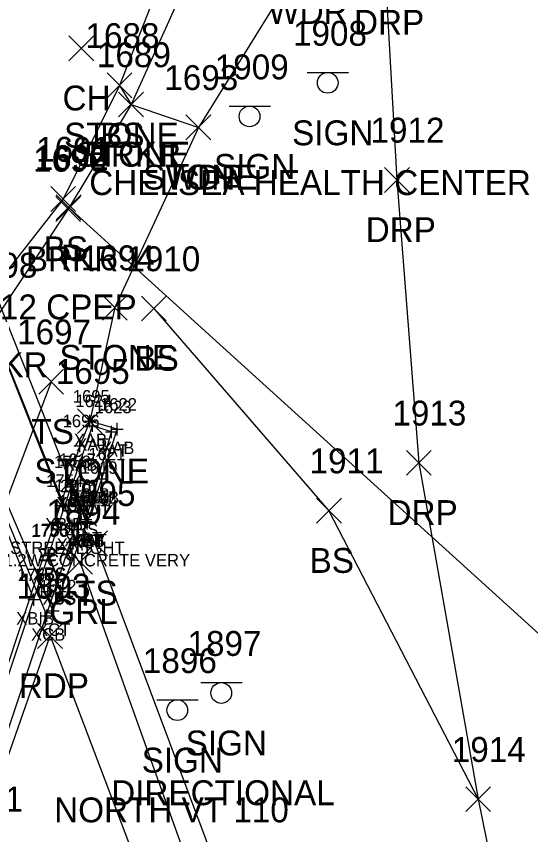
# Model space of a CAD drawing. Extents: x 1651305 to 1654558, y 539481 to 548441.
# Drawn here: x 1654353.9 to 1654395.2, y 544608.3 to 544674.1 of the extents above; entities that cross this region are included whole.
import ezdxf

# ---------------------------------------------------------------- set-up
doc = ezdxf.new("R2010")
doc.units = 0
for name, color, linetype in [('B_A', 7, 'Continuous'), ('B_C', 7, 'Continuous'), ('B_I', 7, 'Continuous'), ('B_TIC', 7, 'Continuous'), ('BB', 7, 'Continuous'), ('BDC', 7, 'Continuous'), ('BF', 7, 'Continuous'), ('BR', 7, 'Continuous'), ('BSE', 7, 'Continuous'), ('BSUBM', 7, 'Continuous'), ('D_A', 7, 'Continuous'), ('D_C', 7, 'Continuous'), ('D_I', 7, 'Continuous'), ('D_TIC', 7, 'Continuous'), ('DCP', 7, 'Continuous'), ('L_A', 7, 'Continuous'), ('L_I', 7, 'Continuous'), ('L_TIC', 7, 'Continuous'), ('LASF', 7, 'Continuous'), ('LAWA', 7, 'Continuous'), ('LAWE', 7, 'Continuous'), ('LELB', 7, 'Continuous'), ('P_A', 7, 'Continuous'), ('P_I', 7, 'Continuous'), ('P_TIC', 7, 'Continuous'), ('PET', 7, 'Continuous'), ('R_A', 7, 'Continuous'), ('R_I', 7, 'Continuous'), ('R_TIC', 7, 'Continuous'), ('RDP', 7, 'Continuous'), ('RGR', 7, 'Continuous'), ('S_A', 7, 'Continuous'), ('S_C', 7, 'Continuous'), ('S_I', 7, 'Continuous'), ('SSGN', 7, 'Continuous')]:
    doc.layers.add(name, color=color, linetype=linetype)

msp = doc.modelspace()

# ---------------------------------------------------------------- linework, layer by layer
at = {"layer": 'B_TIC'}
for p, q in [((1654359.785, 544641.57), (1654359.861, 544641.57)), ((1654359.993, 544641.203), (1654360.069, 544641.203)), ((1654359.993, 544641.203), (1654360.069, 544641.203)), ((1654361.974, 544640.927), (1654362.049, 544640.927)), ((1654361.542, 544640.707), (1654361.618, 544640.707)), ((1654358.994, 544639.588), (1654359.069, 544639.588)), ((1654360.754, 544636.929), (1654360.83, 544636.929)), ((1654358.254, 544636.307), (1654358.329, 544636.307)), ((1654358.396, 544636.474), (1654358.471, 544636.474)), ((1654358.396, 544636.474), (1654358.471, 544636.474)), ((1654360.131, 544635.843), (1654360.207, 544635.843)), ((1654357.622, 544634.79), (1654357.698, 544634.79)), ((1654358.058, 544634.399), (1654358.133, 544634.399)), ((1654359.05, 544634.353), (1654359.125, 544634.353)), ((1654359.462, 544633.672), (1654359.538, 544633.672)), ((1654358.367, 544633.155), (1654358.443, 544633.155)), ((1654359.477, 544633.501), (1654359.552, 544633.501)), ((1654359.477, 544633.501), (1654359.552, 544633.501)), ((1654359.477, 544633.501), (1654359.552, 544633.501)), ((1654359.565, 544633.364), (1654359.64, 544633.364)), ((1654359.606, 544633.46), (1654359.681, 544633.46)), ((1654356.437, 544630.766), (1654356.512, 544630.766)), ((1654356.476, 544630.821), (1654356.551, 544630.821)), ((1654357.233, 544628.812), (1654357.308, 544628.812)), ((1654357.272, 544628.867), (1654357.347, 544628.867)), ((1654355.297, 544627.225), (1654355.372, 544627.225)), ((1654356.325, 544625.929), (1654356.401, 544625.929)), ((1654356.819, 544626.314), (1654356.894, 544626.314))]:
    msp.add_line(p, q, dxfattribs=at)
for points in [[(1654359.282, 544641.57), (1654360.282, 544641.57)], [(1654359.782, 544641.07), (1654359.782, 544642.07)], [(1654359.99, 544640.703), (1654359.99, 544641.703)], [(1654359.99, 544640.703), (1654359.99, 544641.703)], [(1654359.49, 544641.203), (1654360.49, 544641.203)], [(1654359.49, 544641.203), (1654360.49, 544641.203)], [(1654361.47, 544640.927), (1654362.47, 544640.927)], [(1654361.539, 544640.207), (1654361.539, 544641.207)], [(1654361.97, 544640.427), (1654361.97, 544641.427)], [(1654361.039, 544640.707), (1654362.039, 544640.707)], [(1654358.49, 544639.588), (1654359.49, 544639.588)], [(1654358.99, 544639.088), (1654358.99, 544640.088)], [(1654358.392, 544635.974), (1654358.392, 544636.974)], [(1654358.392, 544635.974), (1654358.392, 544636.974)], [(1654360.251, 544636.929), (1654361.251, 544636.929)], [(1654360.751, 544636.429), (1654360.751, 544637.429)], [(1654357.75, 544636.307), (1654358.75, 544636.307)], [(1654357.892, 544636.474), (1654358.892, 544636.474)], [(1654357.892, 544636.474), (1654358.892, 544636.474)], [(1654358.25, 544635.807), (1654358.25, 544636.807)], [(1654360.128, 544635.343), (1654360.128, 544636.343)], [(1654359.628, 544635.843), (1654360.628, 544635.843)], [(1654357.619, 544634.29), (1654357.619, 544635.29)], [(1654358.054, 544633.899), (1654358.054, 544634.899)], [(1654357.119, 544634.79), (1654358.119, 544634.79)], [(1654357.554, 544634.399), (1654358.554, 544634.399)], [(1654358.546, 544634.353), (1654359.546, 544634.353)], [(1654359.046, 544633.853), (1654359.046, 544634.853)], [(1654358.364, 544632.655), (1654358.364, 544633.655)], [(1654358.959, 544633.672), (1654359.959, 544633.672)], [(1654359.459, 544633.172), (1654359.459, 544634.172)], [(1654359.473, 544633.001), (1654359.473, 544634.001)], [(1654359.473, 544633.001), (1654359.473, 544634.001)], [(1654359.473, 544633.001), (1654359.473, 544634.001)], [(1654359.561, 544632.864), (1654359.561, 544633.864)], [(1654359.602, 544632.96), (1654359.602, 544633.96)], [(1654357.864, 544633.155), (1654358.864, 544633.155)], [(1654358.973, 544633.501), (1654359.973, 544633.501)], [(1654358.973, 544633.501), (1654359.973, 544633.501)], [(1654358.973, 544633.501), (1654359.973, 544633.501)], [(1654359.061, 544633.364), (1654360.061, 544633.364)], [(1654359.102, 544633.46), (1654360.102, 544633.46)], [(1654356.433, 544630.266), (1654356.433, 544631.266)], [(1654356.472, 544630.321), (1654356.472, 544631.321)], [(1654355.933, 544630.766), (1654356.933, 544630.766)], [(1654355.972, 544630.821), (1654356.972, 544630.821)], [(1654357.229, 544628.312), (1654357.229, 544629.312)], [(1654357.268, 544628.367), (1654357.268, 544629.367)], [(1654356.729, 544628.812), (1654357.729, 544628.812)], [(1654356.768, 544628.867), (1654357.768, 544628.867)], [(1654355.293, 544626.725), (1654355.293, 544627.725)], [(1654354.793, 544627.225), (1654355.793, 544627.225)], [(1654356.322, 544625.429), (1654356.322, 544626.429)], [(1654356.815, 544625.814), (1654356.815, 544626.814)], [(1654355.822, 544625.929), (1654356.822, 544625.929)], [(1654356.315, 544626.314), (1654357.315, 544626.314)]]:
    msp.add_lwpolyline(points, dxfattribs=at)
at = {"layer": 'BB'}
for points in [[(1654329.217, 544706.64), (1654357.619, 544634.79)], [(1654326.61, 544699.426), (1654355.293, 544627.225)]]:
    msp.add_lwpolyline(points, dxfattribs=at)
at = {"layer": 'BDC'}
for points in [[(1654329.215, 544710.048), (1654328.717, 544711.198), (1654325.904, 544702.843), (1654343.99, 544656.168), (1654356.815, 544626.314), (1654359.561, 544633.364), (1654359.473, 544633.501)], [(1654325.775, 544701.967), (1654343.848, 544655.963), (1654356.322, 544625.929)]]:
    msp.add_lwpolyline(points, dxfattribs=at)
at = {"layer": 'BF'}
msp.add_lwpolyline([(1654329.215, 544710.048), (1654348.537, 544660.985), (1654359.473, 544633.501)], dxfattribs=at)
at = {"layer": 'BR'}
msp.add_lwpolyline([(1654329.215, 544710.048), (1654328.365, 544709.646), (1654348.062, 544658.92), (1654358.364, 544633.155), (1654359.473, 544633.501)], dxfattribs=at)
at = {"layer": 'BSE'}
for points in [[(1654358.25, 544636.307), (1654356.472, 544630.821), (1654356.433, 544630.766), (1654347.804, 544604.941), (1654347.754, 544604.896), (1654344.838, 544596.18), (1654344.825, 544596.158), (1654342.547, 544588.987), (1654343.343, 544587.033), (1654348.55, 544602.942), (1654348.6, 544602.987), (1654357.229, 544628.812), (1654357.268, 544628.867), (1654359.046, 544634.353)], [(1654359.046, 544634.353), (1654358.25, 544636.307)], [(1654357.229, 544628.812), (1654356.433, 544630.766)], [(1654357.268, 544628.867), (1654356.472, 544630.821)]]:
    msp.add_lwpolyline(points, dxfattribs=at)
at = {"layer": 'BSUBM'}
for points in [[(1654359.602, 544633.46), (1654360.751, 544636.929), (1654361.97, 544640.927), (1654359.782, 544641.57), (1654358.99, 544639.588), (1654343.132, 544591.581)], [(1654358.392, 544636.474), (1654359.459, 544633.672), (1654360.128, 544635.843), (1654361.539, 544640.707), (1654359.99, 544641.203)], [(1654358.392, 544636.474), (1654359.99, 544641.203)]]:
    msp.add_lwpolyline(points, dxfattribs=at)
at = {"layer": 'D_TIC'}
for points in [[(1654357.089, 544657.757), (1654359.089, 544659.757)], [(1654359.089, 544657.757), (1654357.089, 544659.757)]]:
    msp.add_lwpolyline(points, dxfattribs=at)
at = {"layer": 'DCP'}
msp.add_lwpolyline([(1654358.089, 544658.757), (1654409.494, 544612.147)], dxfattribs=at)
at = {"layer": 'L_TIC'}
for points in [[(1654358.101, 544670.552), (1654360.101, 544672.552)], [(1654360.101, 544670.552), (1654358.101, 544672.552)], [(1654361.172, 544667.564), (1654363.172, 544669.564)], [(1654363.172, 544667.564), (1654361.172, 544669.564)], [(1654361.172, 544667.564), (1654363.172, 544669.564)], [(1654363.172, 544667.564), (1654361.172, 544669.564)], [(1654362.102, 544666.03), (1654364.102, 544668.03)], [(1654364.102, 544666.03), (1654362.102, 544668.03)], [(1654362.102, 544666.03), (1654364.102, 544668.03)], [(1654364.102, 544666.03), (1654362.102, 544668.03)], [(1654367.514, 544664.191), (1654369.514, 544666.191)], [(1654369.514, 544664.191), (1654367.514, 544666.191)], [(1654367.514, 544664.191), (1654369.514, 544666.191)], [(1654369.514, 544664.191), (1654367.514, 544666.191)], [(1654356.638, 544658.428), (1654358.638, 544660.428)], [(1654358.638, 544658.428), (1654356.638, 544660.428)], [(1654357.045, 544657.626), (1654359.045, 544659.626)], [(1654359.045, 544657.626), (1654357.045, 544659.626)], [(1654360.8, 544649.702), (1654362.8, 544651.702)], [(1654362.8, 544649.702), (1654360.8, 544651.702)], [(1654363.93, 544649.628), (1654365.93, 544651.628)], [(1654365.93, 544649.628), (1654363.93, 544651.628)], [(1654355.673, 544643.744), (1654357.673, 544645.744)], [(1654357.673, 544643.744), (1654355.673, 544645.744)], [(1654358.782, 544640.57), (1654360.782, 544642.57)], [(1654360.782, 544640.57), (1654358.782, 544642.57)], [(1654378.02, 544633.378), (1654380.02, 544635.378)], [(1654380.02, 544633.378), (1654378.02, 544635.378)], [(1654359.198, 544630.754), (1654361.198, 544632.754)], [(1654361.198, 544630.754), (1654359.198, 544632.754)], [(1654390.022, 544610.182), (1654392.022, 544612.182)], [(1654392.022, 544610.182), (1654390.022, 544612.182)]]:
    msp.add_lwpolyline(points, dxfattribs=at)
at = {"layer": 'LASF'}
msp.add_lwpolyline([(1654362.172, 544668.564), (1654363.102, 544667.03), (1654368.514, 544665.191), (1654361.8, 544650.702), (1654359.782, 544641.57)], dxfattribs=at)
at = {"layer": 'LAWA'}
msp.add_lwpolyline([(1654379.782, 544856.85), (1654381.229, 544808.018), (1654382.76, 544783.063), (1654377.997, 544758.08), (1654381.891, 544756.134), (1654381.663, 544736.714), (1654380.899, 544705.776), (1654381.561, 544700.356), (1654376.773, 544678.508), (1654368.514, 544665.191)], dxfattribs=at)
at = {"layer": 'LAWE'}
msp.add_lwpolyline([(1654375.942, 544856.312), (1654377.084, 544805.548), (1654378.901, 544780.845), (1654375.25, 544758.971), (1654375.205, 544735.185), (1654374.977, 544710.304), (1654371.319, 544695.811), (1654368.773, 544679.567), (1654363.102, 544667.03), (1654358.045, 544658.626), (1654352.364, 544650.107), (1654344.898, 544634.32), (1654334.876, 544605.424), (1654326.397, 544588.829), (1654321.275, 544565.187), (1654313.301, 544530.304), (1654300.219, 544501.736), (1654283.171, 544465.466), (1654261.064, 544441.258)], dxfattribs=at)
at = {"layer": 'LELB'}
for points in [[(1654374.336, 544855.823), (1654375.217, 544803.448), (1654375.073, 544780.813), (1654373.472, 544758.468), (1654373.912, 544734.871), (1654373.922, 544712.905), (1654369.617, 544696.27), (1654366.919, 544680.671), (1654362.172, 544668.564), (1654357.638, 544659.428), (1654350.702, 544650.566), (1654343.252, 544636.932), (1654333.619, 544607.274), (1654325.309, 544589.171), (1654319.064, 544565.656), (1654310.743, 544531.111), (1654298.268, 544501.75), (1654282.289, 544466.342), (1654260.011, 544442.906)], [(1654364.93, 544650.628), (1654379.02, 544634.378), (1654391.022, 544611.182)], [(1654356.673, 544644.744), (1654348.436, 544623.035), (1654339.079, 544597.886)], [(1654360.198, 544631.754), (1654372.116, 544599.924), (1654382.811, 544567.633), (1654386.584, 544556.384), (1654391.723, 544539.804)]]:
    msp.add_lwpolyline(points, dxfattribs=at)
at = {"layer": 'P_TIC'}
for points in [[(1654355.582, 544623.309), (1654357.582, 544625.309)], [(1654357.582, 544623.309), (1654355.582, 544625.309)]]:
    msp.add_lwpolyline(points, dxfattribs=at)
at = {"layer": 'PET'}
msp.add_lwpolyline([(1654345.042, 544588.36), (1654350.59, 544607.191), (1654356.582, 544624.309), (1654366.692, 544597.705), (1654378.699, 544565.627), (1654388.798, 544536.019), (1654394.392, 544506.433), (1654399.121, 544481.008), (1654401.125, 544462.893), (1654401.531, 544436.346), (1654401.825, 544421.309), (1654397.366, 544359.696), (1654394.392, 544336.586), (1654391.404, 544308.963), (1654388.941, 544290.736), (1654386.845, 544274.06), (1654380.974, 544229.445), (1654377.749, 544202.908), (1654375.628, 544181.037), (1654372.192, 544149.754), (1654366.612, 544105.723), (1654362.798, 544072.788)], dxfattribs=at)
at = {"layer": 'R_TIC'}
for points in [[(1654383.483, 544659.968), (1654385.483, 544661.968)], [(1654385.483, 544659.968), (1654383.483, 544661.968)], [(1654385.242, 544637.223), (1654387.242, 544639.223)], [(1654387.242, 544637.223), (1654385.242, 544639.223)], [(1654357.986, 544629.265), (1654359.986, 544631.265)], [(1654359.986, 544629.265), (1654357.986, 544631.265)], [(1654390.022, 544610.182), (1654392.022, 544612.182)], [(1654392.022, 544610.182), (1654390.022, 544612.182)]]:
    msp.add_lwpolyline(points, dxfattribs=at)
at = {"layer": 'RDP'}
msp.add_lwpolyline([(1654389.401, 544756.56), (1654387.7, 544737.059), (1654385.299, 544704.988), (1654383.543, 544677.638), (1654384.483, 544660.968), (1654386.242, 544638.223), (1654391.022, 544611.182), (1654397.72, 544578.233), (1654402.202, 544552.331), (1654401.972, 544539.048), (1654399.157, 544531.466), (1654397.052, 544530.18)], dxfattribs=at)
at = {"layer": 'RGR'}
msp.add_lwpolyline([(1654358.986, 544630.265), (1654369.998, 544599.511), (1654381.164, 544566.937), (1654383.241, 544561.31), (1654386.584, 544556.384), (1654392.02, 544552.375)], dxfattribs=at)
at = {"layer": 'SSGN'}
for p, q in [((1654377.268, 544669.606), (1654380.602, 544669.606)), ((1654378.915, 544668.772), (1654378.915, 544668.772)), ((1654370.983, 544666.904), (1654374.316, 544666.904)), ((1654372.629, 544666.071), (1654372.629, 544666.071)), ((1654368.707, 544620.557), (1654372.04, 544620.557)), ((1654365.171, 544619.176), (1654368.504, 544619.176)), ((1654370.353, 544619.723), (1654370.353, 544619.723)), ((1654366.817, 544618.343), (1654366.817, 544618.343))]:
    msp.add_line(p, q, dxfattribs=at)
for centre in [(1654378.915, 544668.772), (1654372.629, 544666.071), (1654370.353, 544619.723), (1654366.817, 544618.343)]:
    msp.add_circle(centre, 0.833, dxfattribs=at)

# ---------------------------------------------------------------- texts
at = {"layer": 'B_A'}
for s, p in [('XAB', (1654358.502, 544639.57)), ('XAT', (1654358.694, 544639.203)), ('XAT', (1654358.694, 544639.203)), ('XAT', (1654360.244, 544638.707)), ('XAB', (1654360.691, 544638.927)), ('XAB', (1654357.711, 544637.588)), ('XAB', (1654359.471, 544634.929)), ('XBS', (1654356.991, 544634.307)), ('XAT', (1654357.097, 544634.474)), ('XAT', (1654357.097, 544634.474)), ('XAT', (1654358.833, 544633.843)), ('XBIB', (1654356.19, 544632.79)), ('XSF', (1654356.814, 544632.399)), ('XBS', (1654357.786, 544632.353)), ('XFAT', (1654357.729, 544631.501)), ('XAT', (1654358.163, 544631.672)), ('XCT', (1654358.194, 544631.501)), ('XRF', (1654358.233, 544631.501)), ('XCT', (1654358.282, 544631.364)), ('XAB', (1654358.323, 544631.46)), ('XRF', (1654357.124, 544631.155)), ('XBS', (1654355.173, 544628.766)), ('XBS', (1654355.212, 544628.821)), ('XBS', (1654355.969, 544626.812)), ('XBS', (1654356.008, 544626.867)), ('XBIB', (1654353.864, 544625.225)), ('XCT', (1654355.536, 544624.314)), ('XCB', (1654355.058, 544623.929))]:
    msp.add_text(s, height=1, dxfattribs=at).set_placement(p)
at = {"layer": 'B_C'}
for s, p in [('STREETLIGHT', (1654353.374, 544630.899)), ('XRF 3.3H X 1.2W CONCRETE VERY', (1654345.338, 544629.899))]:
    msp.add_text(s, height=1, dxfattribs=at).set_placement(p)
at = {"layer": 'B_I'}
for s, p in [('1695', (1654358.412, 544643.07)), ('1624', (1654358.62, 544642.703)), ('1624', (1654358.62, 544642.703)), ('1622', (1654360.6, 544642.427)), ('1623', (1654360.169, 544642.207)), ('1696', (1654357.593, 544641.088)), ('1753', (1654356.904, 544637.807)), ('1617', (1654357.306, 544637.974)), ('1617', (1654357.306, 544637.974)), ('1621', (1654359.664, 544638.429)), ('1619', (1654359.038, 544637.343)), ('1754', (1654356.272, 544636.29)), ('1616', (1654356.94, 544635.899)), ('2276', (1654357.389, 544635.853)), ('1618', (1654358.372, 544635.172)), ('1613', (1654357.277, 544634.655)), ('1620', (1654358.189, 544634.96)), ('1615', (1654358.387, 544635.001)), ('1615', (1654358.387, 544635.001)), ('1615', (1654358.387, 544635.001)), ('1614', (1654358.475, 544634.864)), ('1756', (1654355.059, 544632.266)), ('1755', (1654355.126, 544632.321)), ('2274', (1654355.599, 544630.312)), ('2275', (1654355.638, 544630.367)), ('1757', (1654353.947, 544628.725)), ('1611', (1654355.519, 544627.429)), ('1612', (1654355.729, 544627.814))]:
    msp.add_text(s, height=1, dxfattribs=at).set_placement(p)
at = {"layer": 'D_A'}
msp.add_text('P', height=2, dxfattribs=at).set_placement((1654357.467, 544653.757))
at = {"layer": 'D_C'}
msp.add_text('12 CPEP', height=2, dxfattribs=at).set_placement((1654352.554, 544649.757))
at = {"layer": 'D_I'}
msp.add_text('1692', height=2, dxfattribs=at).set_placement((1654355.349, 544661.757))
at = {"layer": 'L_A'}
for s, p in [('WDR', (1654374.135, 544673.508)), ('CH', (1654357.589, 544666.552)), ('STONE', (1654357.716, 544663.564)), ('BS', (1654360.613, 544663.564)), ('STONE', (1654358.645, 544662.03)), ('BRKR', (1654359.693, 544662.03)), ('STONE', (1654364.058, 544660.191)), ('WDR', (1654365.876, 544660.191)), ('BS', (1654356.079, 544654.428)), ('BRKR', (1654354.636, 544653.626)), ('STONE', (1654357.343, 544645.702)), ('BS', (1654363.371, 544645.628)), ('BRKR', (1654348.955, 544645.107)), ('TS', (1654355.083, 544639.744)), ('STONE', (1654355.325, 544636.57)), ('BS', (1654377.461, 544629.378)), ('TS', (1654358.608, 544626.754))]:
    msp.add_text(s, height=2, dxfattribs=at).set_placement(p)
at = {"layer": 'L_I'}
for s, p in [('1688', (1654359.432, 544671.564)), ('1688', (1654359.432, 544671.564)), ('1689', (1654360.354, 544670.03)), ('1689', (1654360.354, 544670.03)), ('1693', (1654365.774, 544668.191)), ('1693', (1654365.774, 544668.191)), ('1691', (1654355.465, 544662.428)), ('1690', (1654355.219, 544661.626)), ('1694', (1654359.06, 544653.702)), ('1910', (1654362.718, 544653.628)), ('1698', (1654349.624, 544653.107)), ('1697', (1654353.933, 544647.744)), ('1695', (1654357.042, 544644.57)), ('1911', (1654377.461, 544637.378)), ('1895', (1654357.506, 544634.754)), ('1914', (1654388.896, 544614.182))]:
    msp.add_text(s, height=2, dxfattribs=at).set_placement(p)
at = {"layer": 'P_A'}
msp.add_text('RDP', height=2, dxfattribs=at).set_placement((1654354.07, 544619.309))
at = {"layer": 'P_I'}
for s, p in [('1893', (1654353.889, 544627.309)), ('1891', (1654348.464, 544610.191)), ('1891', (1654348.464, 544610.191))]:
    msp.add_text(s, height=2, dxfattribs=at).set_placement(p)
at = {"layer": 'R_A'}
for s, p in [('DRP', (1654381.032, 544672.638)), ('DRP', (1654381.971, 544655.968)), ('DRP', (1654383.73, 544633.223)), ('GRL', (1654356.529, 544625.265))]:
    msp.add_text(s, height=2, dxfattribs=at).set_placement(p)
at = {"layer": 'R_I'}
for s, p in [('1912', (1654382.357, 544663.968)), ('1913', (1654384.116, 544641.223)), ('1894', (1654356.293, 544633.265)), ('1914', (1654388.896, 544614.182))]:
    msp.add_text(s, height=2, dxfattribs=at).set_placement(p)
at = {"layer": 'S_A'}
for p in [(1654376.053, 544663.752), (1654369.767, 544661.051), (1654367.491, 544614.703), (1654363.955, 544613.323)]:
    msp.add_text('SIGN', height=2, dxfattribs=at).set_placement(p)
at = {"layer": 'S_C'}
for s, p in [('CHELSEA HEALTH CENTER', (1654359.739, 544659.752)), ('DIRECTIONAL', (1654361.5, 544610.703)), ('NORTH VT 110', (1654356.916, 544609.323))]:
    msp.add_text(s, height=2, dxfattribs=at).set_placement(p)
at = {"layer": 'S_I'}
for s, p in [('1908', (1654376.124, 544671.752)), ('1909', (1654369.831, 544669.051)), ('1897', (1654367.641, 544622.703)), ('1896', (1654364.05, 544621.323))]:
    msp.add_text(s, height=2, dxfattribs=at).set_placement(p)

doc.saveas('drawing.dxf')
